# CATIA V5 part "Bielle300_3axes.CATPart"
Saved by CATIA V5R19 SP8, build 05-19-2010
Part number: Bielle300_3axes
Publications: "Demi_longueur_bielle", "Rayon_bielle", "Diam_trou_ext", "Diam_trou_int", "Hauteur_Extremite"
Bounding box of the stored display mesh (mm): x -170 to 170, y -20 to 20, z -10 to 10
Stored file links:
  F:\! CONCEPTION\PROJET\Mécanisme 590\CAO\Bielle300_3axes.CATPart
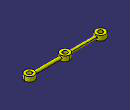
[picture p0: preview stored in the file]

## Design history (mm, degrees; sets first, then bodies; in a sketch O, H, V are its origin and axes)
Parameters
  Demi_longueur_bielle = 150 mm
  Rayon_bielle = 6 mm
  Diam_trou_ext = 40 mm
  Diam_trou_int = 20 mm {= Diam_trou_ext /2}
  Hauteur_Extremite = 10 mm
Body1 (main body)
  Sketch1 on xy-plane, origin (0, 0, 0), H (1, 0, 0), V (0, 1, 0)
    point P1 (-150, 0)
    line L1 (-150, 0) -> (-150, 6)
    line L2 (-150, 6) -> (0, 6)
    line L3 (0, 6) -> (0, 0)
    line L4 (0, 0) -> (-150, 0)
    length L2 = 150 {= Demi_longueur_bielle}
    length L1 = 6 {= Rayon_bielle}
    coincidence: P1 H, L3 V
    vertical: L1 V, L3 V
    horizontal: L2 H, L4 H
  Shaft1: profile Sketch1, axis Sketch1.L4, angle 360
  Sketch2 on xy-plane, origin (0, 0, 0), H (1, 0, 0), V (0, 1, 0)
    circle A1 centre (-150, 0) radius 20
    point P1 (-150, 0)
    reference projected line E1 (-150, 10) -> (-150, -10) from edge [face of Shaft1 from Sketch1.L1 | face of Shaft1 from Sketch1.L2]
    arc A2 centre (0, 0) radius 20 from (0, 20) to (0, -20) ccw
    point P2 (0, 20)
    point P3 (0, -20)
    line L1 (0, 20) -> (0, -20)
    radius A1 = 20 {= Diam_trou_ext /2}
    radius A2 = 20 {= Diam_trou_ext /2}
    coincidence: P1 H, P1 E1, P2 V, P3 V
    vertical: L1 V
  Pad1: profile Sketch2, direction (0, 0, 1), length 10 {= Hauteur_Extremite}, mirrored extent
  Sketch3 on end face of Pad1, origin (0, 0, 10), H (1, 0, 0), V (0, 1, 0)
    circle A1 centre (-150, 0) radius 10
    point P1 (-150, 0)
    reference projected circle E1 centre (-150, 0) radius 20 from edge [face of Pad1 from Sketch2.A1 | end face of Pad1]
    arc A2 centre (0, 0) radius 10 from (0, 10) to (0, -10) ccw
    point P2 (0, 10)
    point P3 (0, -10)
    line L1 (0, 10) -> (0, -10)
    radius A1 = 10 {= Diam_trou_int /2}
    radius A2 = 10 {= Diam_trou_int /2}
    coincidence: P1 H, P2 V, P3 V
    concentricity: A1 E1
    vertical: L1 V
  Pocket1: profile Sketch3, direction (0, 0, -1), through (limit type 6)
  Mirror1: of Shaft1, Sketch1, Pad1, Sketch2, Pocket1, Sketch3, about yz-plane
